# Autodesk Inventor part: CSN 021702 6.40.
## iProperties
Shininess: 20.0
Length Units: 11269
Angle Units: 11279
Time Units: 11290
Mass Units: 11283
Length Display Precision: 3
Angle Display Precision: 2
Created: 2001-01
Part Number: CSN 021702 6.40.
Material: Steel, Mild
Document SubType Name: Modeling
Description: Washer B 6.40 CSN 021702.
Standard: CSN 021702
Density: 7.86
Volumn: 0.294524311274043
Area: 4.319689898685966
PropertySet Name: Model Information
Control State: 0
Master: False
Checked Out: False
BOM1: Washer B
BOM2: 6.40
BOM3: CSN 021702
+MSCProtocol1+ProtocolID: P08052013552706249
+MSCProtocol2+Protocol: P08052013552706249<@PID>[Data]<@EL>Ds=6{mm<@EL>d=6.4{mm<@EL>Dd=12{mm<@EL>h=1.6{mm<@EL>mass=0.000994{kg<@EL>[Globals]<@EL>BOM1=Washer B<@EL>BOM2=6.40<@EL>BOM3=CS
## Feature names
1. ExtrusionBlind1
2. Hole1
